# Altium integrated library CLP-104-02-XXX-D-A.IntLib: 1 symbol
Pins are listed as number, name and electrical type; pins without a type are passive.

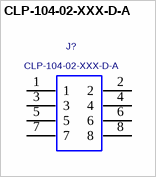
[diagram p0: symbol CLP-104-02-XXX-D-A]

## CLP-104-02-XXX-D-A
designator J?
Socket, Double Row, Surface Mount, 0.050"x0.050" Pitch, 8 Pins.; MANUFACTURER: SAMTEC
footprint CLP-104-02-XXX-D-A
pins: 1, 2, 3, 4, 5, 6, 7, 8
